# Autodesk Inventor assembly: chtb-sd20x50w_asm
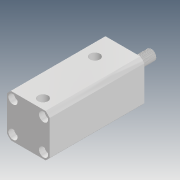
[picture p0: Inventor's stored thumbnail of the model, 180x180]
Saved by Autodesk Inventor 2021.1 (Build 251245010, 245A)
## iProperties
Company: Microsoft
Created: 2018-05
Part Number: chtb-sd20x50w_asm
Description: STEP AP214
Document SubType Name: Assembly
Designer: user
Title: chtb-sd20x50w_asm.STEP
Author: Windows
Revision Number: ÈÎºÎ
Sending System: SolidWorks 2015
Preprocessor: SwSTEP 2.0
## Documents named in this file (4)
- D:\Vault_2016\Projekty\Clamptek\Hydraulic\CHTB\CHTB-20\Inventor\CHTB-SD20x50W\chtb-sd20x50w_asm.iam
- D:\Vault_2016\Projekty\Clamptek\Hydraulic\CHTB\CHTB-20\Inventor\CHTB-SD20x50W\CHTB-SD20X50NBT.ipt
- D:\Vault_2016\Projekty\Clamptek\Hydraulic\CHTB\CHTB-20\Inventor\CHTB-SD20x50W\CHTB-SD20X50WHSG.ipt
- D:\Vault_2016\Projekty\Clamptek\Hydraulic\CHTB\CHTB-20\Inventor\CHTB-SD20x50W\QG.ipt
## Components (3 placed, 3 different names)
1. CHTB-SD20X50NBT_1
2. CHTB-SD20X50WHSG_2
3. QG_3
